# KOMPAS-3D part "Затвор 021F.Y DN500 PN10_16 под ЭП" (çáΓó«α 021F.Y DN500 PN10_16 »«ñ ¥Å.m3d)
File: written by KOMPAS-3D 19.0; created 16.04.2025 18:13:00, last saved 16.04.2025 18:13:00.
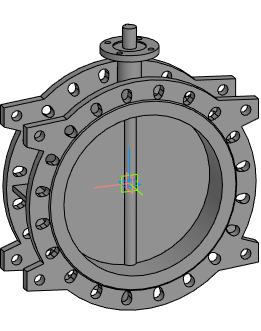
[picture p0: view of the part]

Document properties: Автор: Евгений; Полное имя файла: E:\Dendor Работа Сачек\3D для проекитирвщиков\1.6 Тип 021F.Y Затвор дисковый поворотный фланцевый\stp_Тип 021F.Y Затвор  DN40 PN10_16 под ЭП\Затвор 021F.Y DN500 PN10_16 под ЭП.m3d

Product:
- Part/product: Затвор 021F.Y DN500 PN10_16 под ЭП

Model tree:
1. Операция без истории:1  (labels: Затвор 021F.Y DN500 PN10_16 под ЭП)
